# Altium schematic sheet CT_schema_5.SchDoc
size 298 x 247 mm
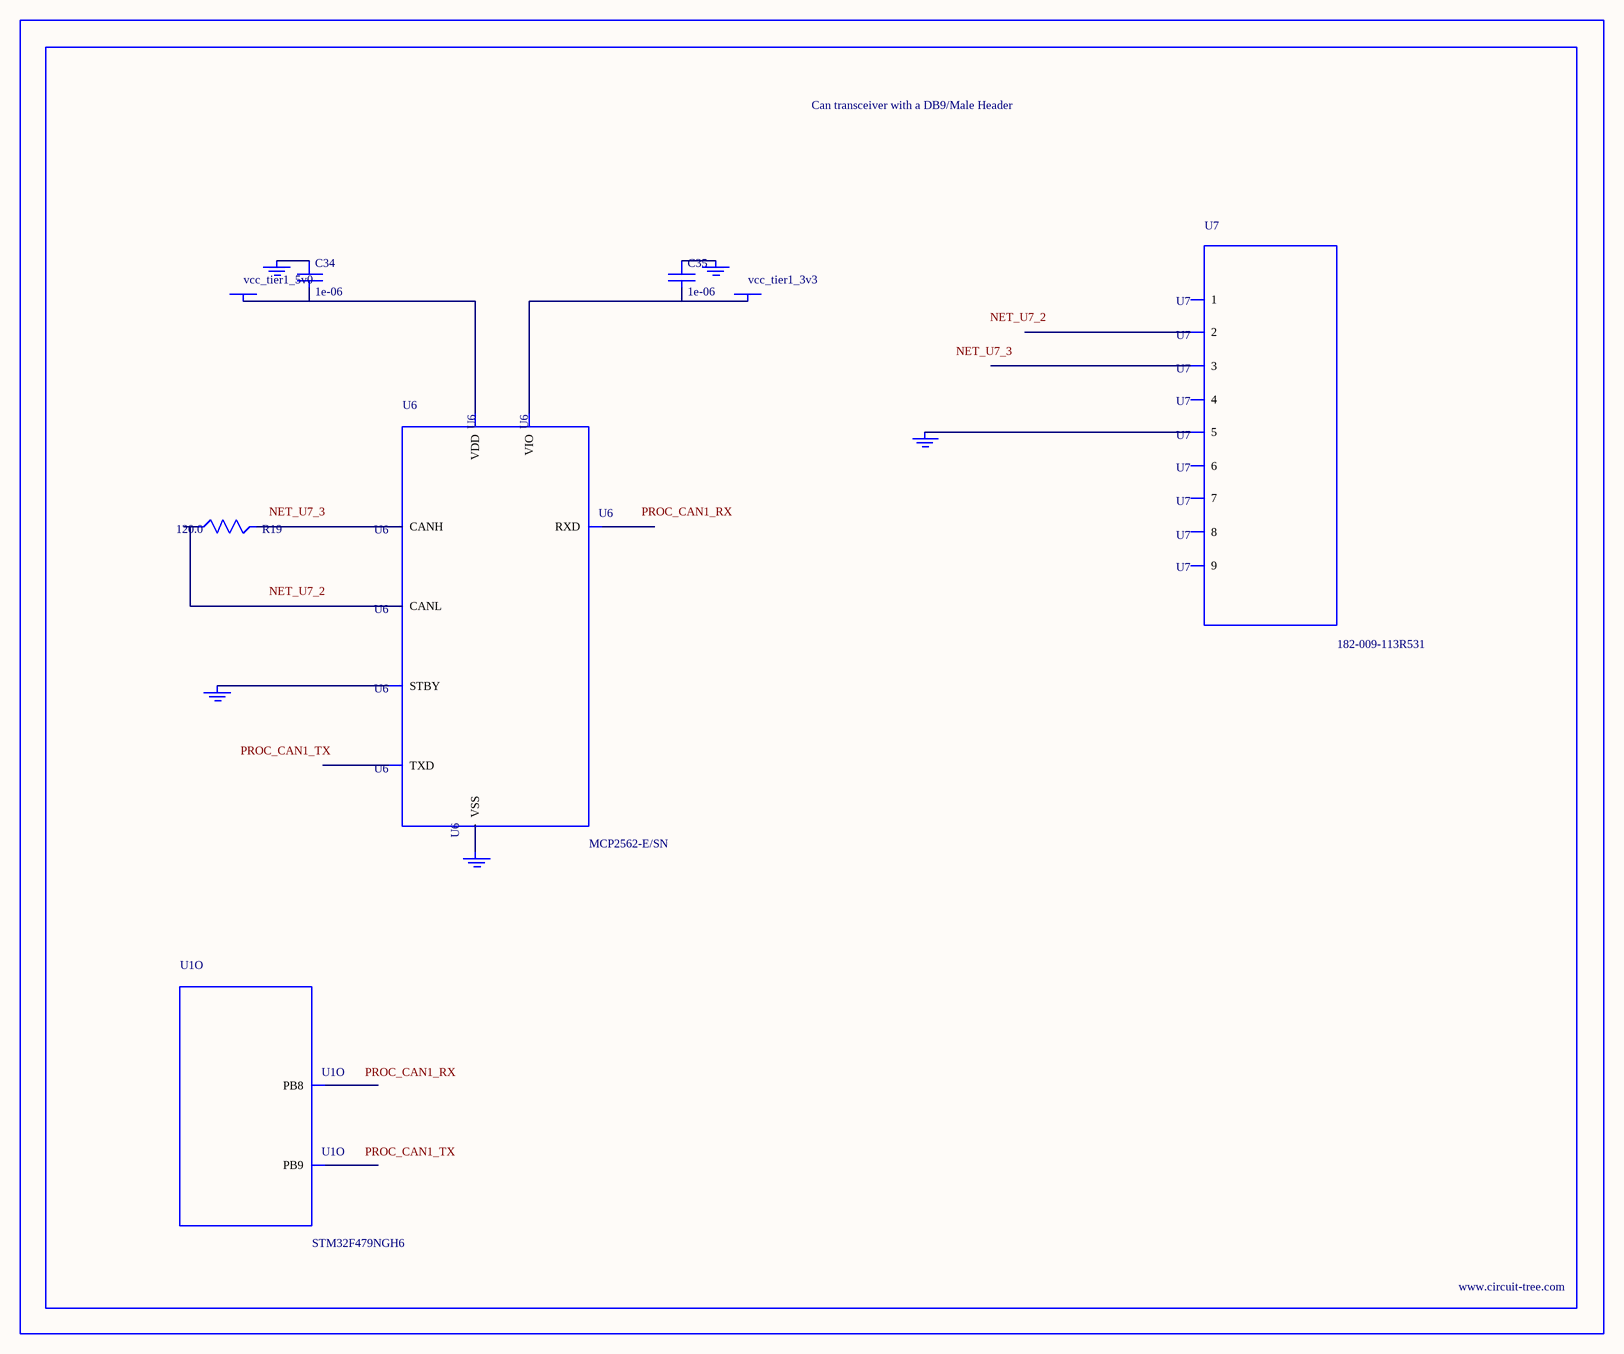
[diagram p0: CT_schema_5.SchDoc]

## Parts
BORDER4  (no value)
C34  1e-06  [C0603]
C35  1e-06  [C0603]
GND_INSTANCE_4_0  (no value)
GND_INSTANCE_4_1  (no value)
GND_INSTANCE_4_2  (no value)
GND_INSTANCE_4_3  (no value)
GND_INSTANCE_4_4  (no value)
POWER_INSTANCE_4_0  vcc_tier1_5v0
POWER_INSTANCE_4_1  vcc_tier1_3v3
R19  120.0  [R0603]
U1  STM32F479NGH6  [TFBGA216]  (part O of 15)
U6  MCP2562-E/SN  [SOIC-8]
U7  182-009-113R531  [182-009-MALE]

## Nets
NetC34_1: C34.1 GND_INSTANCE_4_0.0(GND)
NetC34_2: C34.2 POWER_INSTANCE_4_0.0(PWR) U6.3(VDD)
NetC35_1: C35.1 GND_INSTANCE_4_1.0(GND)
NetC35_2: C35.2 POWER_INSTANCE_4_1.0(PWR) U6.5(VIO)
NetGND_INSTANCE_4_2_0: GND_INSTANCE_4_2.0(GND) U6.8(STBY)
NetGND_INSTANCE_4_3_0: GND_INSTANCE_4_3.0(GND) U6.2(VSS)
NetGND_INSTANCE_4_4_0: GND_INSTANCE_4_4.0(GND) U7.5
NetR19_1: R19.1 U6.6(CANL)
NetR19_2: R19.2 U6.7(CANH)

Not connected (* = marked no-connect by the designer): U1 A7(PB8) B4(PB9); U6 1(TXD) 4(RXD); U7 1 2 3 4 6 7 8 9

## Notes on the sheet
- Labels drawn without touching a wire or pin: NET_U7_2, NET_U7_3, PROC_CAN1_RX, PROC_CAN1_TX

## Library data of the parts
BORDER4 = BORDER_PAGE4
C34 C35 = C0603C105K3RACTU
GND_INSTANCE_4_0-GND_INSTANCE_4_4 = GND
POWER_INSTANCE_4_0 POWER_INSTANCE_4_1 = PWR
R19 = RC0603JR-07120RL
